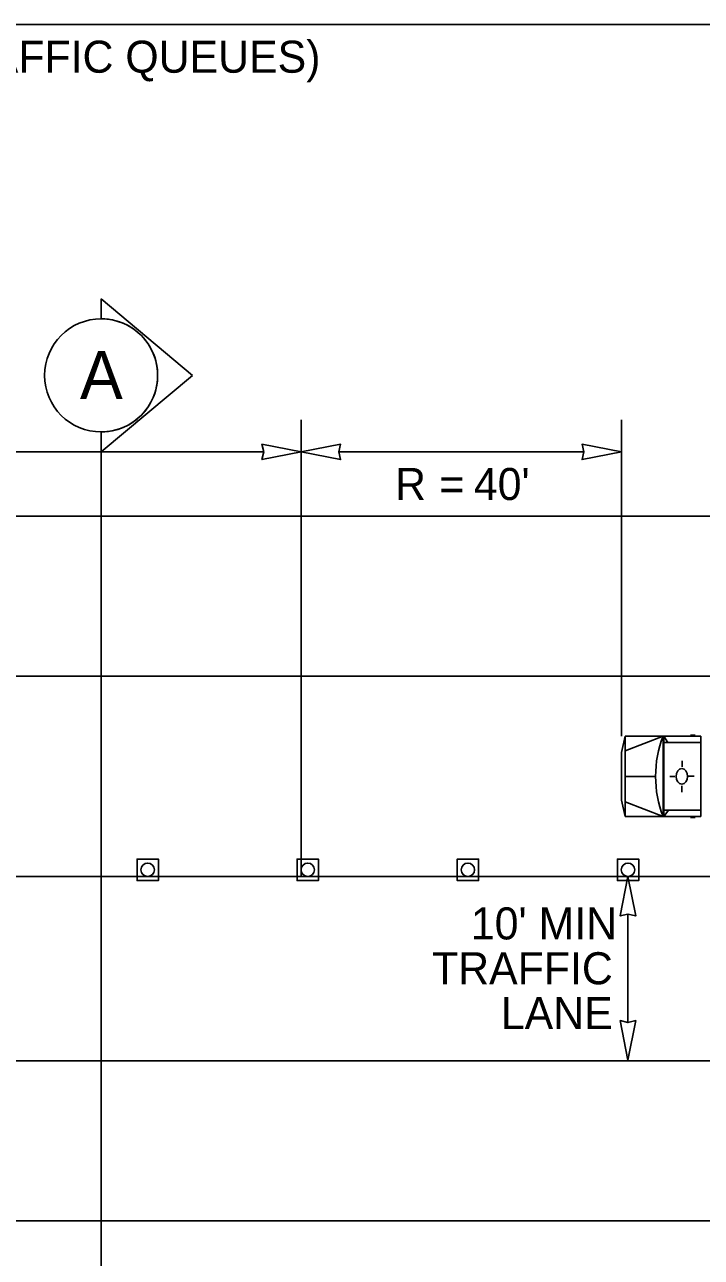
# Model space of a CAD drawing. Extents: x 99999.1 to 100095.7, y 99995 to 100010.7.
# Drawn here: x 100049.243 to 100050.933, y 100005.641 to 100008.719 of the extents above; entities that cross this region are included whole.
import ezdxf

# ---------------------------------------------------------------- set-up
doc = ezdxf.new("R2010")
doc.units = 0
for name, color, linetype in [('RD_ED_ShoulderPavedEdge', 7, 'Continuous'), ('RD_MK_LineEdgeWhite', 7, 'Continuous'), ('RD_MK_LineSkipCenter', 7, 'Continuous'), ('SH_TI_WZSectionCut', 7, 'Continuous'), ('TR_WZ_ProtectiveVehicle', 7, 'Continuous'), ('TR_WZ_TrafficCone', 7, 'Continuous'), ('TR_WZ_WorkZoneDetails', 7, 'Continuous'), ('TR_WZ_WorkZoneTextCurrent', 7, 'Continuous')]:
    doc.layers.add(name, color=color, linetype=linetype)

msp = doc.modelspace()

# ---------------------------------------------------------------- linework, layer by layer
at = {"layer": 'RD_ED_ShoulderPavedEdge'}
for p, q in [((100040.1076, 100007.4923), (100055.6424, 100007.4923)), ((100040.1076, 100005.7323), (100055.6424, 100005.7323))]:
    msp.add_line(p, q, dxfattribs=at)
at = {"layer": 'RD_MK_LineEdgeWhite'}
for p, q in [((100040.1076, 100007.0923), (100055.6424, 100007.0923)), ((100040.1076, 100006.1323), (100055.6424, 100006.1323))]:
    msp.add_line(p, q, dxfattribs=at)
at = {"layer": 'RD_MK_LineSkipCenter'}
msp.add_lwpolyline([(100051.15, 100006.5923), (100043.4767, 100006.5923)], dxfattribs=at)
at = {"layer": 'SH_TI_WZSectionCut'}
for p, q in [((100049.4337, 100007.9847), (100049.4337, 100008.0346)), ((100049.4337, 100008.0346), (100049.6619, 100007.8435)), ((100049.6619, 100007.8435), (100049.4337, 100007.6523)), ((100049.4337, 100007.6523), (100049.4337, 100007.7022)), ((100049.4338, 100007.7022), (100049.4338, 100005.5723))]:
    msp.add_line(p, q, dxfattribs=at)
msp.add_circle((100049.4338, 100007.8435), 0.1412, dxfattribs=at)
msp.add_arc((100049.4338, 100007.8435), 0.1412, 269.9978, 90.0022, dxfattribs=at)
at = {"layer": 'TR_WZ_ProtectiveVehicle'}
for p, q in [((100050.743, 100006.9423), (100050.7338, 100006.902)), ((100050.743, 100006.7423), (100050.743, 100006.9423)), ((100050.743, 100006.9423), (100050.9319, 100006.9423)), ((100050.743, 100006.9057), (100050.8375, 100006.9423)), ((100050.8375, 100006.7423), (100050.8375, 100006.9423)), ((100050.8392, 100006.7423), (100050.8392, 100006.9423)), ((100050.8492, 100006.9268), (100050.8392, 100006.9423)), ((100050.9062, 100006.9451), (100050.9175, 100006.9451)), ((100050.9319, 100006.7423), (100050.9319, 100006.9423)), ((100050.8392, 100006.9268), (100050.9319, 100006.9268)), ((100050.7338, 100006.7827), (100050.7338, 100006.902)), ((100050.8852, 100006.8808), (100050.885, 100006.8658)), ((100050.743, 100006.8423), (100050.8189, 100006.8423)), ((100050.8544, 100006.8422), (100050.867, 100006.8423)), ((100050.8986, 100006.8427), (100050.8986, 100006.8427)), ((100050.9154, 100006.8431), (100050.9005, 100006.8427)), ((100050.8845, 100006.8027), (100050.8845, 100006.8188)), ((100050.743, 100006.7423), (100050.7338, 100006.7827)), ((100050.743, 100006.779), (100050.8375, 100006.7423)), ((100050.8392, 100006.7423), (100050.8512, 100006.7578)), ((100050.8392, 100006.7578), (100050.9319, 100006.7578)), ((100050.743, 100006.7423), (100050.9319, 100006.7423)), ((100050.9062, 100006.7395), (100050.9175, 100006.7395))]:
    msp.add_line(p, q, dxfattribs=at)
msp.add_ellipse((100050.9725, 100006.8424), major_axis=(0, -0.2099), ratio=0.73155, start_param=4.215852, end_param=5.209111, dxfattribs=at)
msp.add_ellipse((100050.8845, 100006.8423), major_axis=(0, 0.0193), ratio=0.73155, dxfattribs=at)
at = {"layer": 'TR_WZ_TrafficCone'}
for points in [[(100049.5234, 100006.6357), (100049.5767, 100006.6357), (100049.5767, 100006.5823), (100049.5234, 100006.5823), (100049.5234, 100006.6357)], [(100049.5234, 100006.5823), (100049.5767, 100006.5823), (100049.5767, 100006.6357), (100049.5234, 100006.6357), (100049.5234, 100006.5823)], [(100049.9234, 100006.6357), (100049.9767, 100006.6357), (100049.9767, 100006.5823), (100049.9234, 100006.5823), (100049.9234, 100006.6357)], [(100049.9234, 100006.5823), (100049.9767, 100006.5823), (100049.9767, 100006.6357), (100049.9234, 100006.6357), (100049.9234, 100006.5823)], [(100050.3234, 100006.6357), (100050.3767, 100006.6357), (100050.3767, 100006.5823), (100050.3234, 100006.5823), (100050.3234, 100006.6357)], [(100050.3234, 100006.5823), (100050.3767, 100006.5823), (100050.3767, 100006.6357), (100050.3234, 100006.6357), (100050.3234, 100006.5823)], [(100050.7234, 100006.6357), (100050.7767, 100006.6357), (100050.7767, 100006.5823), (100050.7234, 100006.5823), (100050.7234, 100006.6357)], [(100050.7234, 100006.5823), (100050.7767, 100006.5823), (100050.7767, 100006.6357), (100050.7234, 100006.6357), (100050.7234, 100006.5823)]]:
    msp.add_lwpolyline(points, dxfattribs=at)
for centre in [(100049.55, 100006.609), (100049.95, 100006.609), (100050.35, 100006.609), (100050.75, 100006.609)]:
    msp.add_circle(centre, 0.0167, dxfattribs=at)
at = {"layer": 'TR_WZ_WorkZoneDetails'}
for p, q in [((100051.3796, 100008.7191), (100044.3704, 100008.7191)), ((100049.9338, 100007.4923), (100049.9338, 100007.7323)), ((100050.7338, 100006.9423), (100050.7338, 100007.7323)), ((100045.2437, 100007.6523), (100049.84, 100007.6523)), ((100050.64, 100007.6523), (100050.0275, 100007.6523)), ((100050.75, 100006.2278), (100050.75, 100006.4986))]:
    msp.add_line(p, q, dxfattribs=at)
for points in [[(100049.9338, 100007.6523), (100049.8355, 100007.6331), (100049.84, 100007.6523), (100049.8355, 100007.6716)], [(100049.9338, 100007.6523), (100050.032, 100007.6331), (100050.0275, 100007.6523), (100050.032, 100007.6716)], [(100050.7338, 100007.6523), (100050.6355, 100007.6331), (100050.64, 100007.6523), (100050.6355, 100007.6716)], [(100045.15, 100007.4923), (100045.15, 100006.5923), (100049.9338, 100006.5923), (100049.9338, 100007.4923)], [(100050.75, 100006.5923), (100050.7308, 100006.4941), (100050.75, 100006.4986), (100050.7693, 100006.4941)], [(100050.75, 100006.1341), (100050.7308, 100006.2324), (100050.75, 100006.2278), (100050.7693, 100006.2324)]]:
    msp.add_lwpolyline(points, close=True, dxfattribs=at)

# ---------------------------------------------------------------- texts
at = {"layer": 'SH_TI_WZSectionCut'}
msp.add_text('A', height=0.12, rotation=359.99, dxfattribs=at).set_placement((100049.3808, 100007.7843))
at = {"layer": 'TR_WZ_WorkZoneTextCurrent'}
for s, p in [('(MINIMIZE DISTANCE BETWEEN MAINLINE AFADs TO MINIMIZE DELAYS & TRAFFIC QUEUES)', (100045.1911, 100008.5991)), ('R', (100050.1681, 100007.5323)), ("40'", (100050.365, 100007.5323)), ('=', (100050.2786, 100007.5323)), ("10' MIN", (100050.3575, 100006.4352)), ('TRAFFIC', (100050.2604, 100006.3232)), ('LANE', (100050.4323, 100006.2112))]:
    msp.add_text(s, height=0.08, dxfattribs=at).set_placement(p)

doc.saveas('drawing.dxf')
